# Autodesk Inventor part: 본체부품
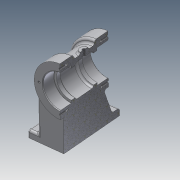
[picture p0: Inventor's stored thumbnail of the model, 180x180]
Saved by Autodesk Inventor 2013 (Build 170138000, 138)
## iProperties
Created: 2020-06
Part Number: 본체부품
Material: 알루미늄 6061
Document SubType Name: Modeling
Designer: CADCOM
Density: 1 g/cm^3
Author: CADCOM
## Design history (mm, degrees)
sketch "스케치1"
  geometry: C1 r 35 at (0, 0); 1 further point
  constraints: 1 centre point, 1 coincident
  dimensions: "d0" = 70 diameter of C1
extrude "돌출1" new body sketch "스케치1" distance "d1" = 22; taper "d2" = 0 deg
sketch "스케치2"
  geometry: C1 r 35 at (0, 0) reference; C2 r 29 at (0, 0)
  constraints: 1 centre point, 1 coincident
  dimensions: "d3" = 58 diameter of C2
extrude "돌출2" join sketch "스케치2" distance "d4" = 34; taper "d5" = 0 deg
sketch "스케치3"
  geometry: C1 r 29 at (0, 0) reference; C2 r 35 at (0, 0)
  constraints: 1 centre point, 1 coincident
  dimensions: "d6" = 70 diameter of C2
extrude "돌출3" join sketch "스케치3" distance "d7" = 22; taper "d8" = 0 deg
node "작업 평면1"
sketch "스케치4"
  geometry: L1 (-35, 0)-(35, 0) reference; L2 (35, 0)-(35, -22) reference; L3 (-35, 0)-(-35, -22) reference; L4 (-35, -78)-(35, -78) reference; L5 (-35, -56)-(-35, -78) reference; L6 (35, -56)-(35, -78) reference; L7 (0, 0)-(0, -5); L8 (49, -5)-(-49, -5); L9 (-49, -5)-(-49, -95); L10 (-49, -95)-(49, -95); L11 (49, -95)-(49, -5)
  constraints: 10 end point, 3 parallel, 1 horizontal, 1 midpoint, 1 perpendicular
  dimensions: "d10" = 5 distance of L7.end L7.start; "d11" = 98 distance of L10.end L9.end; "d12" = 90 distance of L9.end L8.end
extrude "돌출4" join sketch "스케치4" distance "d13" = 10; taper "d14" = 0 deg
sketch "스케치5"
  geometry: L1 (-35, -22)-(-35, 0) reference; L2 (-35, 0)-(35, 0) reference; L3 (35, 0)-(35, -22) reference; L4 (35, -22)-(29, -22) reference; L5 (29, -22)-(29, -56) reference; L6 (29, -56)-(35, -56) reference; L7 (35, -56)-(35, -78) reference; L8 (35, -78)-(-35, -78) reference; L9 (-35, -78)-(-35, -56) reference; L10 (-35, -56)-(-29, -56) reference; L11 (-29, -56)-(-29, -22) reference; L12 (-29, -22)-(-35, -22) reference; L13 (-80, -5)-(-70, -5) reference; L14 (-70, -5)-(-70, -95) reference; L15 (-70, -95)-(-80, -95) reference; L16 (-80, -95)-(-80, -5) reference; L17 (-70, -95)-(-70, -83); L18 (-70, -83)-(-35, -70.261); L19 (-70, -83)-(-32.754, -83); 1 further point
  constraints: 6 end point, 2 point on line, 1 equal length, 1 horizontal
  dimensions: "d15" = 12 distance of L14.end L17.end; "d16" = 20 deg angle of L19 L18
  node "절단 모서리 투영1"
sketch "스케치6"
  geometry: L1 (-49, 5)-(49, 5) reference; L2 (-35, 5)-(35, 5); L3 (35, 5)-(35, 15); L4 (35, 15)-(-35, 15); L5 (-35, 15)-(-35, 5); 2 further points
  constraints: 8 end point, 2 midpoint, 2 parallel, 1 horizontal, 1 perpendicular
  dimensions: "d17" = 70 distance of L4.end L3.end; "d18" = 10 distance of L3.end L2.end
extrude "돌출5" join sketch "스케치6" stored distance "d19" = 0; taper "d20" = 0 deg
feature "리브1" dims "d21" = 1, "d22" = 10, "d23" = 0, "d24" = 0, "d25" = 1, "d26" = 1
sketch "스케치7"
  geometry: C1 r 35 at (0, 0) reference; C2 r 23.5 at (0, 0)
  constraints: 1 centre point, 1 coincident
  dimensions: "d27" = 47 diameter of C2
extrude "돌출6" cut sketch "스케치7" distance "d28" = 18; taper "d29" = 0 deg
sketch "스케치8"
  geometry: C1 r 23.5 at (0, 0) reference; C2 r 20 at (0, 0)
  constraints: 1 centre point, 1 coincident
  dimensions: "d30" = 40 diameter of C2
extrude "돌출7" cut sketch "스케치8" distance "d31" = 6; taper "d32" = 0 deg
sketch "스케치9"
  geometry: C1 r 20 at (0, 0) reference; C2 r 23 at (0, 0)
  constraints: 1 centre point, 1 coincident
  dimensions: "d33" = 46 diameter of C2
extrude "돌출8" cut sketch "스케치9" distance "d34" = 30; taper "d35" = 0 deg
sketch "스케치10"
  geometry: C1 r 35 at (0, 0) reference; C2 r 23.5 at (0, 0)
  constraints: 1 centre point, 1 coincident
  dimensions: "d36" = 47 diameter of C2
extrude "돌출9" cut sketch "스케치10" distance "d37" = 18; taper "d38" = 0 deg
sketch "스케치11"
  geometry: C1 r 23.5 at (0, 0) reference; C2 r 20 at (0, 0)
  constraints: 1 centre point, 1 coincident
  dimensions: "d39" = 40 diameter of C2
extrude "돌출10" cut sketch "스케치11" distance "d40" = 6; taper "d41" = 0 deg
sketch "스케치12"
  geometry: C1 r 35 at (0, 0) reference; A1 r 28.5 centre (0, 0) between (0, 28.5) and (0, -28.5); 2 further points
  constraints: 4 point on circle, 1 centre point, 1 coincident
  dimensions: "d42" = 57 diameter of A1
hole "구멍1" sketch "스케치12" at (0, 28.5), (0, -28.5), (28.5, 0), (-28.5, 0) diameter "d43" = 3.242; stored, may be unused: countersink angle "d47" = 90 deg, drill point angle "d49" = 118 deg; dims "d44" = 10, "d45" = 4, "d46" = 2, "d48" = 12
sketch "스케치13"
  geometry: C1 r 35 at (0, 0) reference; A1 r 28.5 centre (0, 0) between (0, 28.5) and (28.5, 0); 2 further points
  constraints: 4 point on circle, 1 centre point, 1 coincident
  dimensions: "d50" = 57 diameter of A1
hole "구멍2" sketch "스케치13" at (0, 28.5), (28.5, 0), (0, -28.5), (-28.5, 0) diameter "d51" = 3.242; stored, may be unused: countersink angle "d55" = 90 deg, drill point angle "d57" = 118 deg; dims "d52" = 10, "d53" = 4, "d54" = 2, "d56" = 12
node "작업 평면2"
sketch "스케치14"
  geometry: L1 (0, 0)-(0, -39); C1 r 6 at (0, -39)
  constraints: 2 end point, 1 centre point, 1 coincident, 1 vertical
  dimensions: "d59" = 39 distance of L1.start L1.end; "d60" = 12 diameter of C1
extrude "돌출11" join sketch "스케치14" stored distance "d61" = 6; taper "d62" = 0 deg
sketch "스케치15"
  geometry: C1 r 6 at (0, 0) reference; 2 further points
  constraints: 1 coincident
hole "구멍3" sketch "스케치15" at (0, 0) diameter "d63" = 5.188; stored, may be unused: countersink angle "d67" = 90 deg, drill point angle "d69" = 0 deg; dims "d64" = 10, "d65" = 4, "d66" = 2, "d68" = 12
fillet "모깎기1" dims "d70" = 20
sketch "스케치16"
  geometry: L1 (29, 95)-(-29, 95) reference; L2 (-29, 75)-(-29, 39); L3 (29, 75)-(29, 39); A1 r 20 centre (-29, 75) between (-29, 95) and (-49, 75) reference; A2 r 20 centre (29, 75) between (49, 75) and (29, 95) reference; 5 further points
  constraints: 4 coincident, 4 end point, 1 parallel, 1 perpendicular
  dimensions: "d71" = 36 distance of L2.start L2.end; "d72" = 36 distance of L3.start L3.end
hole "구멍4" sketch "스케치16" at (-29, 75), (-29, 39), (29, 39), (29, 75) diameter "d73" = 9; stored, may be unused: countersink angle "d77" = 90 deg, drill point angle "d79" = 0 deg; dims "d74" = 10, "d75" = 4, "d76" = 2, "d78" = 12
chamfer "모따기1" distance "d80" = 1; stored, may be unused: second distance "d81" = 2, angle "d82" = 45 deg
fillet "모깎기2" dims "d83" = 0.3
fillet "모깎기4" dims "d85" = 3
fillet "모깎기5" dims "d86" = 3
fillet "모깎기6" dims "d87" = 3
fillet "모깎기7" dims "d88" = 3
fillet "모깎기9" dims "d90" = 3
fillet "모깎기10" dims "d91" = 3
fillet "모깎기11" dims "d92" = 3
sketch "스케치17"
  geometry: L1 (0, 0)-(67, 0) reference; L2 (-3, 7)-(-3, 0) reference; 2 further points
  constraints: 1 other
  dimensions: "d93" = 45 distance from line of L2 point (42, 4); "d94" = 4 distance from line of L1 point (42, 4)
feature "엠보싱1" sketch "스케치17" dims "d0" = 70, "d95" = 0.5, "d96" = 0
fillet "모깎기12" dims "d97" = 3
fillet "모깎기13" dims "d98" = 3
node "솔리드1"
other parameters: "d58" = 32
